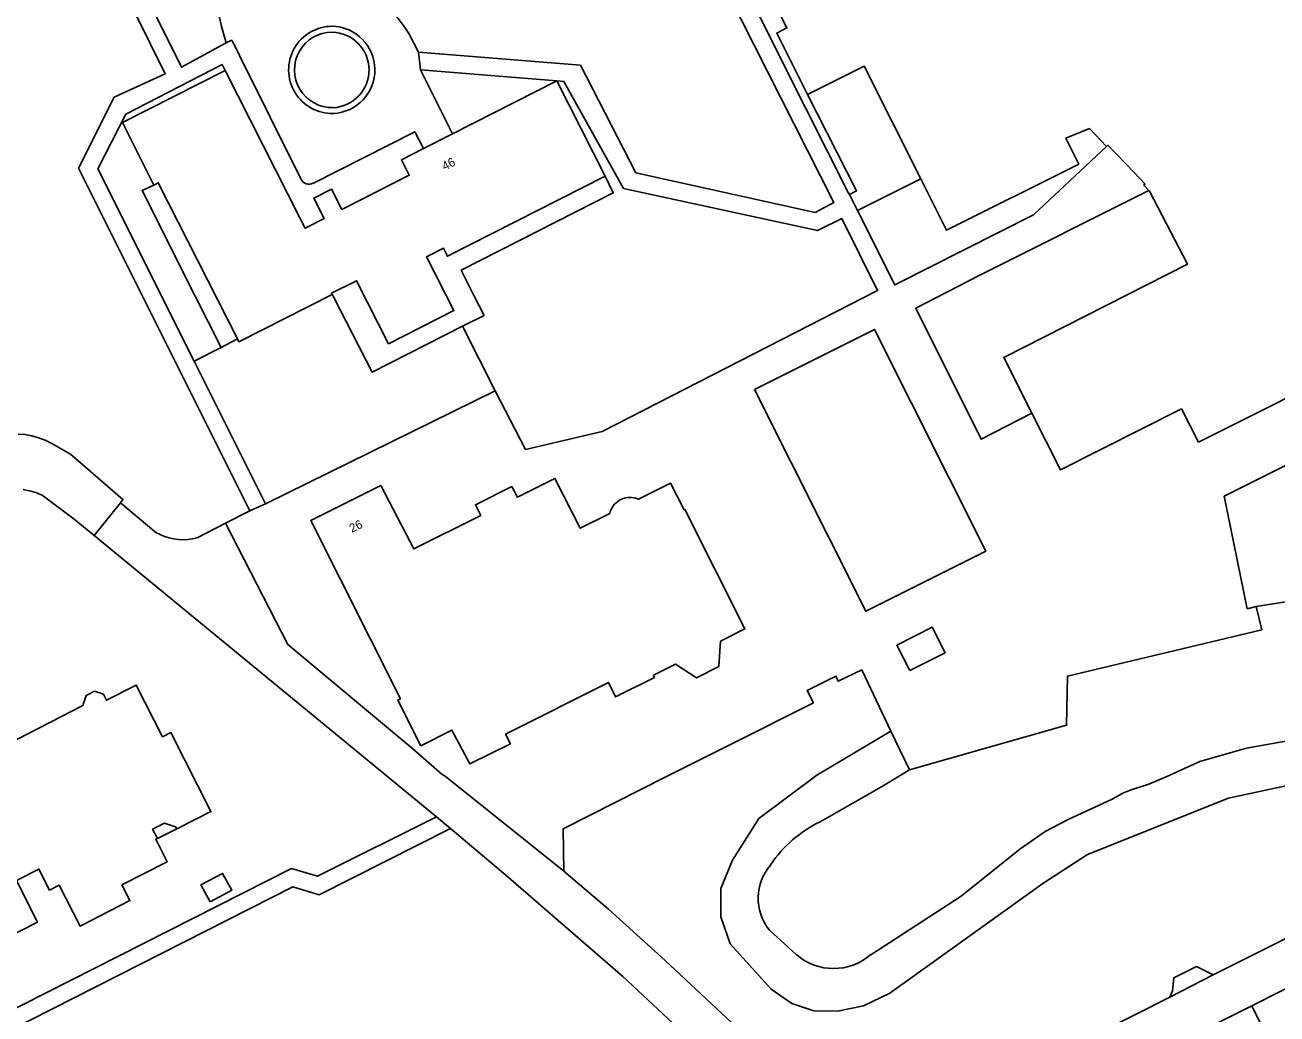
# Model space of a CAD drawing. Extents: x 158132 to 159664, y 385256 to 387218.
# Drawn here: x 158920.9 to 159064.7, y 386417.6 to 386531.1 of the extents above; entities that cross this region are included whole.
import ezdxf

# ---------------------------------------------------------------- set-up
doc = ezdxf.new("R2010")
doc.units = 0
for name, color, linetype in [('IMGEO_Berm_groen', 7, 'Continuous'), ('IMGEO_Groenvoorziening', 7, 'Continuous'), ('IMGEO_Meer_plas_ven_vijver', 7, 'Continuous'), ('IMGEO_Oever', 7, 'Continuous'), ('IMGEO_Pand', 7, 'Continuous'), ('IMGEO_Pand_nummerreeks', 7, 'Continuous'), ('IMGEO_Pand_overbouw', 7, 'Continuous'), ('IMGEO_Parkeervlak_open', 7, 'Continuous'), ('IMGEO_Rijbaan_lokaal_gesloten', 7, 'Continuous'), ('IMGEO_Rijbaan_lokaal_open', 7, 'Continuous'), ('IMGEO_Verkeerseiland_open', 7, 'Continuous'), ('IMGEO_Voetpad_open', 7, 'Continuous')]:
    doc.layers.add(name, color=color, linetype=linetype)

msp = doc.modelspace()

# ---------------------------------------------------------------- linework, layer by layer
at = {"layer": 'IMGEO_Berm_groen'}
msp.add_lwpolyline([(158933.23, 386551.43), (158932.74, 386551.91), (158932.21, 386552.34), (158931.65, 386552.72), (158931.06, 386553.06), (158930.44, 386553.34), (158929.8, 386553.57), (158929.14, 386553.75), (158928.46, 386553.87), (158927.78, 386553.93), (158925.18, 386553.7), (158938.84, 386526.3), (158943.98, 386529.1), (158943.44, 386530.98), (158943.04, 386532.69), (158942.62, 386534.74), (158942.1, 386536.11), (158940.08, 386539.82)], close=True, dxfattribs=at)
at = {"layer": 'IMGEO_Groenvoorziening'}
for points in [[(158920.09, 386484.17), (158920.88, 386484.1), (158921.66, 386483.96), (158922.43, 386483.75), (158923.17, 386483.47), (158923.89, 386483.13), (158926.1, 386481.87), (158932.11, 386476.66), (158931.82, 386476.28), (158935.9, 386472.87), (158936.38, 386472.62), (158936.89, 386472.41), (158937.41, 386472.24), (158937.94, 386472.12), (158938.49, 386472.05), (158939.03, 386472.04), (158939.58, 386472.07), (158940.12, 386472.14), (158940.65, 386472.27), (158943.9, 386473.92), (158946.71, 386475.35), (158927.01, 386514.71), (158931.11, 386522.84), (158936.96, 386525.53), (158923.1, 386553.6)], [(159002.92, 386537.11), (159003.22, 386536.21), (159003.4, 386535.85), (159003.69, 386535.24), (159010.5, 386521.63), (159015.43, 386511.92), (159015.55, 386511.68), (159016.37, 386512.09), (159010.76, 386523.17), (159007.22, 386530.22), (159008.38, 386530.8), (159005.81, 386535.92)], [(158963.68, 386531.94), (158964.35, 386531.09), (158964.95, 386530.18), (158966.06, 386528.04), (158984.67, 386526.52), (158991.03, 386514.18), (159011.64, 386509.6), (159013.75, 386510.75), (159001.57, 386534.92)], [(159095.79, 386495.63), (159058.61, 386477.03), (159061.23, 386464.11), (159062.28, 386464.36), (159066.42, 386465.03)], [(158880.9, 386398.53), (158951.46, 386434.27), (158954.45, 386433.39), (158968.14, 386440.2), (158928.8, 386472.51), (158926.52, 386474.38), (158922.84, 386477.17), (158922.13, 386477.45), (158921.39, 386477.65), (158920.64, 386477.8)], [(159068.17, 386444.32), (159059.08, 386442.37), (159042.9, 386435.88), (159037.76, 386432.56), (159020.21, 386419.95), (159017.17, 386418.5), (159014.2, 386417.9), (159011.48, 386417.94), (159008.93, 386418.79), (159006.56, 386420.41), (159001.86, 386425.64), (159000.77, 386428.72), (159000.8, 386431.97), (159002.13, 386435.24), (159005.17, 386440.01), (159011.8, 386444.98), (159020.33, 386450.04), (159016.99, 386457.09), (159014.28, 386455.78), (159014, 386456.38), (159010.72, 386454.72), (159011.44, 386453.32), (159001.97, 386448.54), (158994.55, 386444.83), (158982.68, 386438.85), (158982.74, 386433.99), (158987.9, 386429.61), (158994.38, 386423.73), (159002.05, 386416.54)], [(158916.25, 386447.23), (158927.52, 386452.98), (158927.89, 386454.13), (158928.86, 386454.63), (158929.87, 386454.3), (158930.23, 386453.6), (158933.64, 386455.34), (158936.68, 386449.41), (158937.6, 386449.88), (158942.22, 386440.82), (158938.3, 386438.82), (158938.17, 386439.08), (158936.9, 386439.49), (158935.53, 386438.79), (158936.08, 386437.72), (158935.89, 386437.64), (158937.21, 386435.05), (158932, 386432.39), (158932.92, 386430.6), (158927.19, 386427.67), (158924.79, 386432.37), (158923.69, 386431.8), (158922.46, 386434.21), (158919.88, 386432.89), (158922.3, 386428.13), (158916.62, 386425.23)], [(158995.27, 386416.5), (158989.53, 386421.87), (158976.11, 386433.53), (158969.75, 386438.88), (158954.64, 386431.27), (158951.64, 386432.17), (158881.22, 386396.45)], [(159032.02, 386409.26), (159052.36, 386419.51), (159052.66, 386420.22), (159052.8, 386421.72), (159055.42, 386423.02), (159057.35, 386422.06), (159076.55, 386431.69)], [(159063.74, 386414.56), (159061.77, 386418.51), (159059.26, 386417.25)]]:
    msp.add_lwpolyline(points, dxfattribs=at)
for points in [[(158932.05, 386519.93), (158943.87, 386525.92), (158943.51, 386526.62), (158932.45, 386520.91), (158929.25, 386514.63), (158940.3, 386492.55), (158943.4, 386494.1), (158940.43, 386500), (158934.32, 386512.12), (158935.67, 386512.77)], [(158981.96, 386524.72), (158966.31, 386526.01), (158969.98, 386518.65)], [(159014.67, 386508.92), (159011.88, 386507.53), (158989.61, 386512.37), (158982.76, 386524.67), (158981.96, 386524.72), (158987.51, 386513.77), (158988.43, 386511.87), (158970.95, 386502.99), (158972.47, 386500), (158973.59, 386497.8), (158971.11, 386496.55), (158974.88, 386489.12), (158978.35, 386482.4), (158987.17, 386484.47), (159018.8, 386500.64)], [(159036.68, 386509.35), (159045.09, 386517.18), (159043.13, 386519.24), (159040.41, 386518.13), (159041.89, 386515.18), (159026.71, 386507.58), (159023.76, 386513.46), (159016.48, 386509.83), (159020.76, 386501.3)], [(159054.38, 386503.67), (159050.02, 386512.07), (159049.94, 386512.15), (159030.44, 386502.38), (159023.17, 386498.62), (159030.7, 386483.57), (159036.52, 386486.58), (159033.29, 386492.97)], [(159004.67, 386489.27), (159017.44, 386463.82), (159031.22, 386470.71), (159018.42, 386496.19)], [(159022.48, 386457), (159026.55, 386459.06), (159025.07, 386461.98), (159021, 386459.92)], [(158942.13, 386430.44), (158941.08, 386432.39), (158943.57, 386433.72), (158944.61, 386431.78)]]:
    msp.add_lwpolyline(points, close=True, dxfattribs=at)
for centre, start, end in [((158956.16, 386525.99), 90.0426, 271.3838), ((158956.04, 386525.98), 272.8949, 88.5315)]:
    msp.add_arc(centre, 4.34, start, end, dxfattribs=at)
at = {"layer": 'IMGEO_Meer_plas_ven_vijver'}
for points in [[(159066.42, 386465.03), (159062.28, 386464.36), (159062.92, 386461.7), (159040.62, 386456.37), (159040.5, 386450.73), (159022.44, 386445.6), (159019.44, 386443.77), (159012.21, 386439.64)], [(159018.01, 386424.38), (159028.41, 386431.11), (159035.12, 386436.48), (159038.02, 386438.54), (159040.67, 386439.91), (159045.74, 386442.24), (159046.97, 386442.94), (159047.93, 386443.32), (159049.93, 386443.95), (159051.93, 386444.8), (159055.81, 386446.55), (159061.17, 386448.08), (159067.17, 386449.18)], [(159006.35, 386427.23), (159009.48, 386424.38)]]:
    msp.add_lwpolyline(points, dxfattribs=at)
for centre, radius, start, end in [((159018.48, 386426.65), 14.43, 115.7503, 146.0424), ((159010.88, 386430.87), 5.81, 138.701, 218.7229), ((159013.74, 386429.28), 6.49, 228.896, 311.104)]:
    msp.add_arc(centre, radius, start, end, dxfattribs=at)
at = {"layer": 'IMGEO_Oever'}
for points in [[(159012.21, 386439.64), (159019.44, 386443.77), (159022.44, 386445.6), (159020.33, 386450.04), (159011.8, 386444.98), (159005.17, 386440.01), (159002.13, 386435.24), (159000.8, 386431.97), (159000.77, 386428.72), (159001.86, 386425.64), (159006.56, 386420.41), (159008.93, 386418.79), (159011.48, 386417.94), (159014.2, 386417.9), (159017.17, 386418.5), (159020.21, 386419.95), (159037.76, 386432.56), (159042.9, 386435.88), (159059.08, 386442.37), (159068.17, 386444.32)], [(159067.17, 386449.18), (159061.17, 386448.08), (159055.81, 386446.55), (159051.93, 386444.8), (159049.93, 386443.95), (159047.93, 386443.32), (159046.97, 386442.94), (159045.74, 386442.24), (159040.67, 386439.91), (159038.02, 386438.54), (159035.12, 386436.48), (159028.41, 386431.11), (159018.01, 386424.38)], [(159009.48, 386424.38), (159006.35, 386427.23)]]:
    msp.add_lwpolyline(points, dxfattribs=at)
for centre, radius, start, end in [((159018.48, 386426.65), 14.43, 115.7503, 146.0424), ((159010.88, 386430.87), 5.81, 138.701, 218.7229), ((159013.74, 386429.28), 6.49, 228.896, 311.104)]:
    msp.add_arc(centre, radius, start, end, dxfattribs=at)
at = {"layer": 'IMGEO_Pand'}
for points in [[(159005.81, 386535.92), (159008.38, 386530.8), (159007.22, 386530.22), (159010.76, 386523.17), (159017.24, 386526.43), (159023.76, 386513.46), (159026.71, 386507.58), (159041.89, 386515.18), (159040.41, 386518.13), (159043.13, 386519.24), (159045.09, 386517.18), (159045.25, 386517.33), (159048.25, 386514.19), (159049.51, 386512.88), (159049.37, 386512.76), (159049.94, 386512.15), (159050.02, 386512.07), (159054.38, 386503.67), (159033.29, 386492.97), (159036.52, 386486.58), (159039.81, 386480.05), (159053.69, 386487.05), (159055.65, 386483.24), (159074.74, 386492.79)], [(158988.03, 386475.04), (158984.64, 386473.35), (158981.74, 386479.08), (158977.42, 386476.94), (158976.77, 386478.13), (158972.61, 386476.05), (158973.22, 386474.82), (158965.53, 386470.98), (158961.72, 386478.28), (158953.68, 386474.23), (158963.99, 386453.77), (158963.7, 386453.62), (158966.34, 386448.38), (158969.91, 386450.17), (158971.95, 386446.28), (158976.62, 386448.6), (158976.06, 386449.72), (158987.87, 386455.64), (158988.7, 386453.99), (158993.17, 386456.23), (158993.05, 386456.47), (158995.57, 386457.76), (158997.98, 386456.17), (159000.56, 386457.49), (159000.74, 386460.37), (159003.55, 386461.79), (158996.67, 386475.51), (158996.57, 386475.47), (158995.01, 386478.52), (158991.33, 386476.68), (158991.04, 386476.8)], [(158916.62, 386425.23), (158922.3, 386428.13), (158919.88, 386432.89), (158922.46, 386434.21), (158923.69, 386431.8), (158924.79, 386432.37), (158927.19, 386427.67), (158932.92, 386430.6), (158932, 386432.39), (158937.21, 386435.05), (158935.89, 386437.64), (158936.08, 386437.72), (158935.53, 386438.79), (158936.9, 386439.49), (158938.17, 386439.08), (158938.3, 386438.82), (158942.22, 386440.82), (158937.6, 386449.88), (158936.68, 386449.41), (158933.64, 386455.34), (158930.23, 386453.6), (158929.87, 386454.3), (158928.86, 386454.63), (158927.89, 386454.13), (158927.52, 386452.98), (158916.25, 386447.23)]]:
    msp.add_lwpolyline(points, dxfattribs=at)
for points in [[(158987.51, 386513.77), (158981.96, 386524.72), (158969.98, 386518.65), (158966.63, 386516.95), (158964.11, 386515.67), (158965.01, 386513.89), (158957.26, 386509.97), (158956.08, 386512.29), (158954.04, 386511.26), (158955.22, 386508.93), (158953.04, 386507.82), (158952.52, 386508.85), (158943.87, 386525.92), (158932.05, 386519.93), (158935.67, 386512.77), (158936.18, 386513.03), (158945.27, 386495.1), (158945.44, 386494.76), (158956.16, 386500.19), (158956.09, 386500.33), (158958.96, 386501.78), (158962.63, 386494.54), (158970.13, 386498.34), (158966.99, 386504.54), (158968.93, 386505.52), (158969.39, 386504.59)], [(158942.13, 386430.44), (158944.61, 386431.78), (158943.57, 386433.72), (158941.08, 386432.39)]]:
    msp.add_lwpolyline(points, close=True, dxfattribs=at)
msp.add_arc((158990.35, 386474.52), 2.38, 73.2469, 167.5544, dxfattribs=at)
at = {"layer": 'IMGEO_Pand_overbouw'}
msp.add_lwpolyline([(158938.3, 386438.82), (158938.17, 386439.08), (158936.9, 386439.49), (158935.53, 386438.79), (158936.08, 386437.72)], close=True, dxfattribs=at)
at = {"layer": 'IMGEO_Parkeervlak_open'}
msp.add_lwpolyline([(159057.35, 386422.06), (159055.42, 386423.02), (159052.8, 386421.72), (159052.66, 386420.22), (159052.36, 386419.51)], close=True, dxfattribs=at)
at = {"layer": 'IMGEO_Rijbaan_lokaal_gesloten'}
for points in [[(158953.94, 386512.96), (158965.64, 386518.87), (158966.63, 386516.95), (158969.98, 386518.65), (158966.31, 386526.01), (158966.06, 386528.04), (158964.95, 386530.18), (158964.35, 386531.09), (158963.68, 386531.94), (158962.93, 386532.73), (158962.11, 386533.44), (158961.24, 386534.09), (158960.31, 386534.65), (158959.33, 386535.12), (158957.55, 386535.57), (158954.69, 386535.69), (158953.77, 386535.77), (158952.87, 386535.93), (158951.98, 386536.16), (158951.11, 386536.47), (158950.27, 386536.85), (158949.47, 386537.29)], [(158943.04, 386532.69), (158943.44, 386530.98), (158943.98, 386529.1), (158944.6, 386529.4), (158944.75, 386529.17), (158944.85, 386528.98), (158945.51, 386527.64), (158952.59, 386513.4)], [(158920.64, 386477.8), (158921.39, 386477.65), (158922.13, 386477.45), (158922.84, 386477.17), (158926.52, 386474.38), (158928.8, 386472.51), (158931.82, 386476.28), (158932.11, 386476.66), (158926.1, 386481.87), (158923.89, 386483.13), (158923.17, 386483.47), (158922.43, 386483.75), (158921.66, 386483.96), (158920.88, 386484.1), (158920.09, 386484.17)]]:
    msp.add_lwpolyline(points, dxfattribs=at)
for centre, radius, start, end in [((158956.16, 386525.99), 5.01, 90.0909, 271.4072), ((158956.04, 386525.99), 5.01, 272.7934, 88.7047), ((158953.48, 386513.84), 0.99, 206.5777, 298.01)]:
    msp.add_arc(centre, radius, start, end, dxfattribs=at)
at = {"layer": 'IMGEO_Rijbaan_lokaal_open'}
for points in [[(159002.05, 386416.54), (158994.38, 386423.73), (158987.9, 386429.61), (158982.74, 386433.99), (158969.11, 386444.87), (158968.79, 386445.09), (158965.43, 386448.01), (158951.06, 386460.02), (158943.9, 386473.92), (158940.65, 386472.27), (158940.12, 386472.14), (158939.58, 386472.07), (158939.03, 386472.04), (158938.49, 386472.05), (158937.94, 386472.12), (158937.41, 386472.24), (158936.89, 386472.41), (158936.38, 386472.62), (158935.9, 386472.87), (158931.82, 386476.28), (158928.8, 386472.51), (158968.14, 386440.2), (158969.75, 386438.88), (158976.11, 386433.53), (158989.53, 386421.87), (158995.27, 386416.5)], [(159076.55, 386431.69), (159057.35, 386422.06), (159052.36, 386419.51), (159032.02, 386409.26), (159020.93, 386403.64), (159023.35, 386398.96), (159024.91, 386399.75), (159025.05, 386399.82), (159026.63, 386400.63), (159050.94, 386413.05), (159059.26, 386417.25), (159061.77, 386418.51), (159078.04, 386426.72)]]:
    msp.add_lwpolyline(points, dxfattribs=at)
at = {"layer": 'IMGEO_Verkeerseiland_open'}
for centre, radius, start, end in [((158956.16, 386525.99), 5.01, 90.0909, 271.4072), ((158956.16, 386525.99), 4.34, 90.0426, 271.3838), ((158956.04, 386525.99), 5.01, 272.7934, 88.7047), ((158956.04, 386525.98), 4.34, 272.8949, 88.5315)]:
    msp.add_arc(centre, radius, start, end, dxfattribs=at)
at = {"layer": 'IMGEO_Voetpad_open'}
for points in [[(158923.1, 386553.6), (158936.96, 386525.53), (158931.11, 386522.84), (158927.01, 386514.71), (158946.71, 386475.35), (158948.49, 386476.17), (158940.3, 386492.55), (158929.25, 386514.63), (158932.45, 386520.91), (158943.51, 386526.62), (158943.87, 386525.92), (158952.52, 386508.85), (158953.04, 386507.82), (158955.22, 386508.93), (158954.04, 386511.26), (158956.08, 386512.29), (158957.26, 386509.97), (158965.01, 386513.89), (158964.11, 386515.67), (158966.63, 386516.95), (158965.64, 386518.87), (158953.94, 386512.96)], [(158944.85, 386528.98), (158944.75, 386529.17), (158944.6, 386529.4), (158943.98, 386529.1), (158938.84, 386526.3), (158925.18, 386553.7)], [(159001.57, 386534.92), (159013.75, 386510.75), (159011.64, 386509.6), (158991.03, 386514.18), (158984.67, 386526.52), (158966.06, 386528.04), (158966.31, 386526.01), (158981.96, 386524.72), (158982.76, 386524.67), (158989.61, 386512.37), (159011.88, 386507.53), (159014.67, 386508.92), (159018.8, 386500.64), (158987.17, 386484.47), (158978.35, 386482.4), (158974.88, 386489.12), (158948.49, 386476.17), (158946.71, 386475.35), (158943.9, 386473.92), (158951.06, 386460.02), (158965.43, 386448.01), (158968.79, 386445.09), (158969.11, 386444.87), (158982.74, 386433.99), (158982.68, 386438.85), (158994.55, 386444.83), (159001.97, 386448.54), (159011.44, 386453.32), (159010.72, 386454.72), (159014, 386456.38), (159014.28, 386455.78), (159016.99, 386457.09), (159020.33, 386450.04), (159022.44, 386445.6), (159040.5, 386450.73), (159040.62, 386456.37), (159062.92, 386461.7), (159062.28, 386464.36), (159061.23, 386464.11), (159058.61, 386477.03), (159095.79, 386495.63)], [(159074.74, 386492.79), (159055.65, 386483.24), (159053.69, 386487.05), (159039.81, 386480.05), (159036.52, 386486.58), (159030.7, 386483.57), (159023.17, 386498.62), (159030.44, 386502.38), (159049.94, 386512.15), (159049.37, 386512.76), (159049.51, 386512.88), (159048.25, 386514.19), (159045.25, 386517.33), (159045.09, 386517.18), (159036.68, 386509.35), (159020.76, 386501.3), (159016.48, 386509.83), (159015.55, 386511.68), (159015.43, 386511.92), (159010.5, 386521.63), (159003.69, 386535.24)], [(158952.59, 386513.4), (158945.51, 386527.64), (158944.85, 386528.98)], [(158991.04, 386476.8), (158991.33, 386476.68), (158995.01, 386478.52), (158996.57, 386475.47), (158996.67, 386475.51), (159003.55, 386461.79), (159000.74, 386460.37), (159000.56, 386457.49), (158997.98, 386456.17), (158995.57, 386457.76), (158993.05, 386456.47), (158993.17, 386456.23), (158988.7, 386453.99), (158987.87, 386455.64), (158976.06, 386449.72), (158976.62, 386448.6), (158971.95, 386446.28), (158969.91, 386450.17), (158966.34, 386448.38), (158963.7, 386453.62), (158963.99, 386453.77), (158953.68, 386474.23), (158961.72, 386478.28), (158965.53, 386470.98), (158973.22, 386474.82), (158972.61, 386476.05), (158976.77, 386478.13), (158977.42, 386476.94), (158981.74, 386479.08)], [(158981.74, 386479.08), (158984.64, 386473.35), (158988.03, 386475.04)]]:
    msp.add_lwpolyline(points, dxfattribs=at)
for points in [[(159017.24, 386526.43), (159010.76, 386523.17), (159016.37, 386512.09), (159015.55, 386511.68), (159016.48, 386509.83), (159023.76, 386513.46)], [(158935.67, 386512.77), (158934.32, 386512.12), (158940.43, 386500), (158943.4, 386494.1), (158945.27, 386495.1), (158936.18, 386513.03)], [(158988.43, 386511.87), (158987.51, 386513.77), (158969.39, 386504.59), (158968.93, 386505.52), (158966.99, 386504.54), (158970.13, 386498.34), (158962.63, 386494.54), (158958.96, 386501.78), (158956.09, 386500.33), (158956.16, 386500.19), (158956.26, 386500), (158960.76, 386491.29), (158971.11, 386496.55), (158973.59, 386497.8), (158972.47, 386500), (158970.95, 386502.99)], [(158971.11, 386496.55), (158960.76, 386491.29), (158956.26, 386500), (158956.16, 386500.19), (158945.44, 386494.76), (158945.27, 386495.1), (158943.4, 386494.1), (158940.3, 386492.55), (158948.49, 386476.17), (158974.88, 386489.12)], [(159004.67, 386489.27), (159018.42, 386496.19), (159031.22, 386470.71), (159017.44, 386463.82)], [(159022.48, 386457), (159021, 386459.92), (159025.07, 386461.98), (159026.55, 386459.06)], [(158838.71, 386385.88), (158839.29, 386384.11), (158854.42, 386391.72), (158860.64, 386389.79), (158876.53, 386397.99), (158881.22, 386396.45), (158951.64, 386432.17), (158954.64, 386431.27), (158969.75, 386438.88), (158968.14, 386440.2), (158954.45, 386433.39), (158951.46, 386434.27), (158880.9, 386398.53), (158876.51, 386400.14), (158860.27, 386391.85), (158854.35, 386393.71)], [(159079.2, 386421.42), (159077.37, 386425.36), (159078.04, 386426.72), (159061.77, 386418.51), (159063.74, 386414.56), (159061.58, 386413.48), (159061.96, 386412.72), (159065.21, 386414.36), (159066.14, 386412.52), (159080.11, 386419.58)]]:
    msp.add_lwpolyline(points, close=True, dxfattribs=at)
for centre, radius, start, end in [((158953.48, 386513.84), 0.99, 206.5777, 298.01), ((158990.35, 386474.52), 2.38, 73.2469, 167.5544)]:
    msp.add_arc(centre, radius, start, end, dxfattribs=at)

# ---------------------------------------------------------------- texts
at = {"layer": 'IMGEO_Pand_nummerreeks'}
for s, rotation, p in [('46', 26.3045, (158969.06, 386514.42)), ('26', 26.3517, (158958.42, 386472.82))]:
    msp.add_text(s, height=1, rotation=rotation, dxfattribs=at).set_placement(p)

doc.saveas('drawing.dxf')
